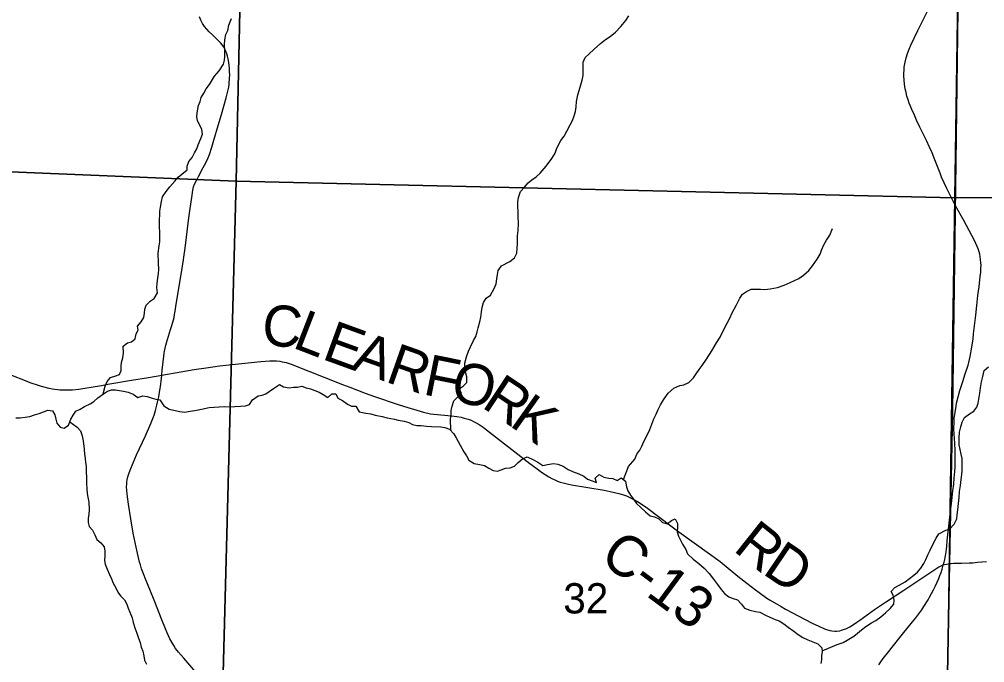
# Model space of a CAD drawing. Extents: x 0 to 34, y 0 to 22.
# Drawn here: x 15.148 to 16.483, y 14.243 to 15.132 of the extents above; entities that cross this region are included whole.
import ezdxf

# ---------------------------------------------------------------- set-up
doc = ezdxf.new("R2010")
doc.units = 0
for name, color, linetype in [('GM_X_Corporation', 7, 'Continuous'), ('GM_X_County_Road', 7, 'Continuous'), ('GM_X_County_Road_Text', 7, 'Continuous'), ('GM_X_Minor_River', 7, 'Continuous'), ('GM_X_Section_Text', 7, 'Continuous'), ('GM_X_Township_Road', 7, 'Continuous')]:
    doc.layers.add(name, color=color, linetype=linetype)

msp = doc.modelspace()

# ---------------------------------------------------------------- linework, layer by layer
at = {"layer": 'GM_X_Corporation'}
for points in [[(16.4214, 13.6), (17.4, 13.6), (17.4, 16.913), (16.5516, 16.9243), (16.4689, 16.9245), (16.4603, 16.2617), (16.4611, 16.1288), (16.4516, 15.5964), (16.4498, 15.4626), (16.4419, 14.8642), (16.438, 14.5908), (16.4339, 14.3806), (16.4212, 13.6609)], [(14.4583, 15.9623), (15.4691, 15.9163), (15.4475, 14.9085), (14.443, 14.9501)], [(15.4691, 15.9163), (16.4563, 15.9084), (16.441, 14.8856), (15.4475, 14.9085)], [(17.4, 14.8906), (17.4, 15.8967), (16.4563, 15.9084), (16.441, 14.8856)], [(14.443, 14.9501), (15.4475, 14.9085), (15.4212, 13.9143), (14.4181, 13.9369)], [(15.4475, 14.9085), (16.441, 14.8856), (16.4262, 13.901), (15.4212, 13.9143)], [(17.4, 13.8871), (17.4, 14.8906), (16.441, 14.8856), (16.4262, 13.901)]]:
    msp.add_lwpolyline(points, close=True, dxfattribs=at)
msp.add_lwpolyline([(10.9052, 15.3502), (10.897, 14.5214), (10.8818, 13.7678), (10.8788, 13.6), (16.4214, 13.6), (16.4212, 13.6609), (16.4339, 14.3806), (16.438, 14.5908), (16.4419, 14.8642), (16.4498, 15.4626)], dxfattribs=at)
at = {"layer": 'GM_X_County_Road'}
for points in [[(16.423, 14.9141), (16.4209, 14.9194), (16.4139, 14.9378), (16.4098, 14.9478), (16.4065, 14.9555), (16.4022, 14.9647), (16.393, 14.9833), (16.3884, 14.993), (16.3854, 14.9996), (16.3819, 15.0075), (16.3799, 15.0122), (16.3784, 15.0161), (16.3766, 15.021), (16.3751, 15.0261), (16.3739, 15.0309), (16.3728, 15.0359), (16.3722, 15.0393), (16.3718, 15.0424), (16.3713, 15.0484), (16.3709, 15.0537), (16.3714, 15.0662), (16.3725, 15.0728), (16.374, 15.0788), (16.376, 15.0851), (16.3781, 15.0907), (16.3805, 15.0965), (16.3902, 15.1169), (16.4059, 15.148)], [(16.442, 14.8754), (16.4303, 14.8983), (16.4264, 14.9063), (16.423, 14.9141)], [(16.4345, 14.4441), (16.4373, 14.4669), (16.4388, 14.4804), (16.4398, 14.4895), (16.4405, 14.4981), (16.4413, 14.507), (16.4416, 14.5133), (16.4419, 14.5212), (16.4418, 14.5361), (16.4413, 14.5462), (16.4402, 14.5656), (16.4403, 14.5758), (16.4406, 14.5804), (16.4408, 14.5832), (16.4417, 14.5887), (16.4431, 14.5976), (16.4438, 14.6014), (16.446, 14.6103), (16.4484, 14.6189), (16.4527, 14.6329), (16.4552, 14.6408), (16.4597, 14.654), (16.4607, 14.6577), (16.4618, 14.6619), (16.4626, 14.6661), (16.4649, 14.6792), (16.4665, 14.6906), (16.4673, 14.6972), (16.4702, 14.723), (16.4717, 14.7365), (16.4733, 14.7504), (16.4748, 14.7624), (16.4764, 14.7766), (16.4771, 14.7827), (16.4775, 14.788), (16.4776, 14.7922), (16.4775, 14.7954), (16.477, 14.8001), (16.4765, 14.8037), (16.4757, 14.8075), (16.4748, 14.811), (16.4736, 14.8147), (16.4723, 14.8181), (16.4704, 14.8225), (16.4685, 14.8263), (16.4537, 14.854), (16.4425, 14.8745), (16.442, 14.8754)], [(15.1366, 14.6403), (15.1556, 14.6327), (15.1622, 14.6303), (15.1737, 14.6263), (15.1776, 14.6252), (15.1885, 14.6225), (15.1936, 14.6215), (15.2037, 14.6201), (15.2058, 14.6199), (15.2209, 14.62), (15.2298, 14.6208), (15.2355, 14.6217), (15.2611, 14.6261), (15.2701, 14.6278), (15.3028, 14.6336), (15.3261, 14.6371), (15.3446, 14.6402), (15.3708, 14.6447), (15.3896, 14.6479), (15.4061, 14.6505), (15.4246, 14.6531), (15.4379, 14.6547), (15.4595, 14.657), (15.4816, 14.6591), (15.4942, 14.66), (15.4987, 14.6601), (15.5033, 14.6599), (15.5079, 14.6595), (15.5112, 14.6589), (15.5164, 14.6577), (15.5208, 14.6564), (15.5237, 14.6554), (15.5944, 14.6276), (15.6047, 14.6235), (15.6261, 14.6153), (15.6386, 14.611), (15.6717, 14.5996), (15.6847, 14.5956), (15.7019, 14.5903), (15.7067, 14.589), (15.7162, 14.587), (15.7208, 14.5863), (15.7451, 14.5841), (15.7527, 14.5832), (15.7585, 14.5822), (15.7628, 14.581), (15.7683, 14.5795), (15.7724, 14.5779), (15.7759, 14.5764), (15.7792, 14.5746), (15.7833, 14.5723), (15.7889, 14.5684), (15.7938, 14.5649), (15.8536, 14.5183), (15.8617, 14.512), (15.8698, 14.5062), (15.875, 14.5028), (15.8797, 14.4999), (15.884, 14.4975), (15.8884, 14.4954), (15.8919, 14.4939), (15.8957, 14.4925), (15.8996, 14.4914), (15.9071, 14.4896), (15.9112, 14.4888), (15.9564, 14.4811), (15.9646, 14.4796), (15.9705, 14.4783), (15.9767, 14.4766), (15.983, 14.4748), (15.9872, 14.4733), (15.9908, 14.4717), (15.9999, 14.4672), (16.0024, 14.4658), (16.0132, 14.4588), (16.0165, 14.4564), (16.0484, 14.4322), (16.0596, 14.4239), (16.1019, 14.3935), (16.1166, 14.3827), (16.1224, 14.3782), (16.1414, 14.3626), (16.1538, 14.3526), (16.1656, 14.3434), (16.1706, 14.3397), (16.1815, 14.3322), (16.186, 14.3293), (16.2012, 14.3203), (16.2072, 14.317), (16.2342, 14.3026), (16.2439, 14.2976), (16.2531, 14.2932), (16.261, 14.2898), (16.264, 14.2887), (16.2687, 14.2873), (16.2711, 14.2868), (16.2754, 14.2864), (16.2777, 14.2865), (16.2822, 14.2871), (16.2847, 14.2877), (16.2887, 14.289), (16.2907, 14.2898), (16.296, 14.2926), (16.2984, 14.294), (16.306, 14.299), (16.3101, 14.3018), (16.3202, 14.3089), (16.3304, 14.3163), (16.3385, 14.322), (16.3467, 14.3273), (16.3693, 14.3423), (16.3776, 14.3477), (16.4194, 14.3753), (16.4205, 14.376), (16.4232, 14.3771), (16.4254, 14.378)], [(16.3361, 14.2397), (16.3388, 14.244), (16.3421, 14.2486), (16.35, 14.2583), (16.3547, 14.2642), (16.3692, 14.2823), (16.3829, 14.2992), (16.3872, 14.3047), (16.3957, 14.3161), (16.3986, 14.3203), (16.4043, 14.3295), (16.4065, 14.3333), (16.4119, 14.3436), (16.4146, 14.3492), (16.4191, 14.3592), (16.4207, 14.3632), (16.4223, 14.3676), (16.4238, 14.3722), (16.4248, 14.3757), (16.4254, 14.378), (16.4264, 14.3817), (16.4274, 14.3855), (16.428, 14.3881), (16.4285, 14.3906), (16.4289, 14.3931), (16.4293, 14.3959), (16.4297, 14.3997), (16.4301, 14.4039), (16.4308, 14.4111), (16.4335, 14.4359), (16.4345, 14.4441)], [(16.4254, 14.378), (16.4272, 14.3786), (16.4299, 14.3792), (16.4323, 14.3796), (16.4332, 14.3797)], [(16.4332, 14.3797), (16.4344, 14.3799), (16.4362, 14.3801), (16.4396, 14.3804), (16.4507, 14.3806), (16.461, 14.3807), (16.4663, 14.381), (16.4729, 14.3816), (16.4786, 14.3823), (16.4851, 14.3829)]]:
    msp.add_lwpolyline(points, dxfattribs=at)
at = {"layer": 'GM_X_Minor_River'}
for points in [[(15.2636, 14.6143), (15.2664, 14.6253), (15.2693, 14.6315), (15.2737, 14.6369), (15.2809, 14.6394), (15.2861, 14.641), (15.2886, 14.6468), (15.2885, 14.6525), (15.2887, 14.6578), (15.2909, 14.6644), (15.2918, 14.6705), (15.2912, 14.6803), (15.2972, 14.6851), (15.3025, 14.6863), (15.308, 14.6907), (15.3094, 14.6972), (15.3119, 14.7025), (15.311, 14.7082), (15.3162, 14.7141), (15.3198, 14.7202), (15.3208, 14.726), (15.3211, 14.7313), (15.3232, 14.737), (15.3287, 14.7425), (15.334, 14.7464), (15.3387, 14.7542), (15.3378, 14.7614), (15.3384, 14.7671), (15.3393, 14.7747), (15.3399, 14.7808), (15.3405, 14.7865), (15.34, 14.7949), (15.3396, 14.8089), (15.3409, 14.8192), (15.3419, 14.8246), (15.3421, 14.8314), (15.3419, 14.8383), (15.3414, 14.8447), (15.3416, 14.8508), (15.3415, 14.8561), (15.3417, 14.8615), (15.3419, 14.8672), (15.3426, 14.8725), (15.3443, 14.8805), (15.3456, 14.887), (15.3508, 14.894), (15.3559, 14.9006), (15.3625, 14.9084), (15.3673, 14.9142), (15.3725, 14.9181), (15.3796, 14.924), (15.3795, 14.9293), (15.382, 14.9355), (15.3867, 14.9413), (15.39, 14.9475), (15.3933, 14.9532), (15.395, 14.9586), (15.3986, 14.9674), (15.4011, 14.9736), (15.4002, 14.98), (15.3974, 14.9857), (15.3942, 14.9917), (15.3933, 14.9977), (15.3935, 15.003), (15.3956, 15.013), (15.3977, 15.0187), (15.3991, 15.0241), (15.4027, 15.0303), (15.406, 15.036), (15.4104, 15.0422), (15.4177, 15.0538), (15.4239, 15.0612), (15.4298, 15.0701), (15.4312, 15.0755), (15.4318, 15.0808), (15.432, 15.0888), (15.4314, 15.0975), (15.432, 15.1036), (15.4333, 15.1112), (15.4358, 15.1166), (15.4375, 15.1243), (15.4411, 15.1335)], [(15.7444, 14.5638), (15.744, 14.5799), (15.7447, 14.5852), (15.7449, 14.5913), (15.7463, 14.5974), (15.7484, 14.6047), (15.7535, 14.6101), (15.7591, 14.6156), (15.7559, 14.6216), (15.7615, 14.6252), (15.7667, 14.6302), (15.7665, 14.6378), (15.7652, 14.6431), (15.7635, 14.6515), (15.7637, 14.6568), (15.7662, 14.6656), (15.7687, 14.6733), (15.7715, 14.6794), (15.7759, 14.6883), (15.7788, 14.6937), (15.7809, 14.7002), (15.7823, 14.7055), (15.7843, 14.714), (15.7857, 14.7205), (15.7866, 14.7277), (15.7876, 14.7338), (15.7894, 14.7407), (15.793, 14.7465), (15.7993, 14.7508), (15.8044, 14.7601), (15.8069, 14.7666), (15.8079, 14.7735), (15.8089, 14.7796), (15.8099, 14.7849), (15.8146, 14.7915), (15.8259, 14.7975), (15.8322, 14.8026), (15.8358, 14.8088), (15.836, 14.8156), (15.8366, 14.8221), (15.8367, 14.8331), (15.8373, 14.8404), (15.8378, 14.8495), (15.8376, 14.8594), (15.8371, 14.8799), (15.8377, 14.886), (15.8409, 14.8941), (15.8461, 14.9003), (15.8512, 14.9061), (15.8564, 14.9104), (15.8624, 14.9144), (15.868, 14.9195), (15.8761, 14.9292), (15.8838, 14.94), (15.8885, 14.947), (15.891, 14.9539), (15.8964, 14.9647), (15.9012, 14.9705), (15.9048, 14.9774), (15.9095, 14.9863), (15.9124, 14.9921), (15.9149, 14.9986), (15.9167, 15.0047), (15.9176, 15.0112), (15.9182, 15.0184), (15.9202, 15.028), (15.922, 15.0337), (15.9241, 15.0418), (15.9258, 15.0483), (15.9272, 15.0544), (15.9274, 15.0597), (15.9273, 15.0658), (15.9274, 15.073), (15.9299, 15.0792), (15.9351, 15.0839), (15.9426, 15.0909), (15.9515, 15.0987), (15.9581, 15.1042), (15.9649, 15.1085), (15.9719, 15.1144), (15.9793, 15.1222), (15.9863, 15.1307), (15.9907, 15.1369)], [(15.983, 14.496), (15.99, 14.5141), (15.9988, 14.5242), (16.0017, 14.5311), (16.0057, 14.5366), (16.0086, 14.5423), (16.0111, 14.5485), (16.0162, 14.5585), (16.0194, 14.565), (16.0223, 14.5727), (16.0251, 14.58), (16.0284, 14.5866), (16.0313, 14.5927), (16.0342, 14.5993), (16.0385, 14.6062), (16.0448, 14.6155), (16.0526, 14.6222), (16.0612, 14.6258), (16.0668, 14.6271), (16.0736, 14.6303), (16.0799, 14.6365), (16.0835, 14.6423), (16.0879, 14.6481), (16.092, 14.6536), (16.0978, 14.6625), (16.1051, 14.674), (16.1117, 14.6849), (16.1168, 14.6926), (16.1211, 14.7014), (16.1266, 14.7122), (16.1302, 14.7192), (16.1334, 14.7265), (16.1392, 14.7376), (16.1439, 14.7465), (16.1479, 14.7523), (16.1532, 14.7559), (16.1599, 14.7591), (16.1671, 14.7593), (16.1724, 14.759), (16.1785, 14.7588), (16.1861, 14.7597), (16.1963, 14.7615), (16.2053, 14.7648), (16.2135, 14.7684), (16.2195, 14.7712), (16.2255, 14.774), (16.2319, 14.7787), (16.2393, 14.785), (16.2445, 14.7916), (16.2511, 14.8005), (16.2551, 14.8075), (16.2568, 14.8132), (16.2604, 14.8205), (16.2637, 14.8271), (16.2684, 14.8336), (16.2724, 14.8429)], [(16.2579, 14.2592), (16.2787, 14.268), (16.287, 14.2709), (16.2926, 14.274), (16.3016, 14.2796), (16.3068, 14.2835), (16.3124, 14.2882), (16.3183, 14.2929), (16.3261, 14.2981), (16.3321, 14.3013), (16.3389, 14.306), (16.3455, 14.3119), (16.3518, 14.3177), (16.357, 14.3236), (16.3576, 14.3293), (16.3559, 14.3361), (16.3535, 14.3414), (16.3583, 14.3468), (16.3643, 14.35), (16.3729, 14.3548), (16.3785, 14.3591), (16.3845, 14.3638), (16.3897, 14.3681), (16.3945, 14.3736), (16.3985, 14.3798), (16.4014, 14.3855), (16.4042, 14.3921), (16.4071, 14.3982), (16.4104, 14.4055), (16.4154, 14.4152), (16.4191, 14.421), (16.4288, 14.4262), (16.4341, 14.4274), (16.4404, 14.4344), (16.444, 14.4417), (16.4446, 14.4471), (16.4456, 14.454), (16.4465, 14.4627), (16.4474, 14.4711), (16.448, 14.4795), (16.4493, 14.4879), (16.4502, 14.4959), (16.4512, 14.5028), (16.4514, 14.5081), (16.4513, 14.5146), (16.4515, 14.5199), (16.4514, 14.5252), (16.4501, 14.5313), (16.4475, 14.5441), (16.4473, 14.5536), (16.4478, 14.5613), (16.4496, 14.5689), (16.4517, 14.5751), (16.4545, 14.5816), (16.4616, 14.5867), (16.4676, 14.5907), (16.472, 14.5961), (16.4734, 14.6015), (16.4751, 14.6099), (16.4761, 14.6152), (16.477, 14.6228), (16.4784, 14.6312), (16.4801, 14.6385), (16.4821, 14.6469), (16.4881, 14.6516)], [(15.1427, 14.5812), (15.1488, 14.5813), (15.1556, 14.5823), (15.162, 14.5832), (15.1688, 14.5856), (15.1748, 14.5873), (15.1808, 14.5894), (15.1872, 14.5918), (15.1933, 14.5908), (15.1965, 14.5856), (15.1981, 14.5795), (15.1994, 14.5738), (15.2041, 14.5686), (15.2098, 14.5669), (15.2154, 14.5712), (15.219, 14.5793), (15.2219, 14.5851), (15.2259, 14.5905), (15.2315, 14.5933), (15.2379, 14.5972), (15.2454, 14.6005), (15.2506, 14.604), (15.2562, 14.6091), (15.264, 14.6146), (15.2696, 14.6182), (15.2749, 14.6199), (15.2806, 14.62), (15.2863, 14.619), (15.2916, 14.618), (15.2981, 14.617), (15.305, 14.6138), (15.3116, 14.6094), (15.3183, 14.6118), (15.3244, 14.6108), (15.3298, 14.6091), (15.3363, 14.6073), (15.342, 14.6063), (15.3475, 14.5981), (15.3548, 14.5933), (15.3697, 14.5899), (15.3762, 14.5893)], [(15.3762, 14.5893), (15.3837, 14.5906), (15.3902, 14.5915), (15.3996, 14.5933), (15.4102, 14.5955), (15.417, 14.596), (15.4238, 14.5966), (15.4314, 14.5968), (15.4397, 14.5966), (15.4458, 14.5971), (15.4534, 14.5973), (15.4606, 14.5979), (15.4658, 14.5999), (15.4702, 14.6061), (15.4781, 14.6116), (15.4834, 14.6125), (15.4886, 14.6145), (15.4991, 14.6217), (15.5073, 14.6272), (15.513, 14.6243), (15.5207, 14.623), (15.5267, 14.6235), (15.5324, 14.6236), (15.5384, 14.6249), (15.5442, 14.6228), (15.5503, 14.6214), (15.5564, 14.6189), (15.5622, 14.6168), (15.5679, 14.6135), (15.5741, 14.6095), (15.58, 14.6145), (15.5854, 14.6147), (15.5882, 14.6087), (15.5947, 14.6054), (15.6013, 14.6002), (15.607, 14.5973), (15.6131, 14.5975), (15.6175, 14.5896), (15.6266, 14.5876), (15.6338, 14.587), (15.6396, 14.5852), (15.6495, 14.5832), (15.6564, 14.5811), (15.6663, 14.5794), (15.6716, 14.578), (15.6796, 14.5767), (15.6861, 14.575), (15.6915, 14.5721), (15.6972, 14.5707), (15.7033, 14.5705), (15.7105, 14.5699), (15.7174, 14.5693), (15.7303, 14.5689), (15.736, 14.5679), (15.7425, 14.5657), (15.7487, 14.5594), (15.7519, 14.5538), (15.7571, 14.5437), (15.7622, 14.5343), (15.7658, 14.529), (15.7693, 14.523), (15.7767, 14.5183), (15.7839, 14.5166), (15.7908, 14.5152), (15.7969, 14.5119), (15.8027, 14.5087), (15.8088, 14.5077), (15.8141, 14.5093), (15.8201, 14.5118), (15.8265, 14.5123), (15.8322, 14.5143), (15.8373, 14.5194), (15.8433, 14.5245), (15.85, 14.5273), (15.8577, 14.5237), (15.8646, 14.5201), (15.8716, 14.5153), (15.878, 14.5166), (15.8863, 14.5184), (15.8924, 14.5174), (15.8997, 14.5145), (15.9066, 14.5101), (15.9128, 14.5072), (15.9212, 14.504), (15.9281, 14.5008), (15.9335, 14.4963), (15.94, 14.4942), (15.9458, 14.4917), (15.9441, 14.4981), (15.9497, 14.5028), (15.9558, 14.4992), (15.9627, 14.4978), (15.9684, 14.4976), (15.9745, 14.4947), (15.9801, 14.4983), (15.9859, 14.4938), (15.9873, 14.4859), (15.9893, 14.4802), (15.9929, 14.4742), (15.9968, 14.469), (16.0011, 14.463)], [(15.2174, 14.5756), (15.2276, 14.5685), (15.2323, 14.5633), (15.2347, 14.5565), (15.2361, 14.5493), (15.2371, 14.5379), (15.2376, 14.5311), (15.2386, 14.525), (15.2391, 14.5197), (15.24, 14.5144), (15.2405, 14.4908), (15.2411, 14.4828), (15.2413, 14.4768), (15.2425, 14.4715), (15.2438, 14.4647), (15.2441, 14.454), (15.2439, 14.4483), (15.2429, 14.4422), (15.2426, 14.4365), (15.2443, 14.4312), (15.2486, 14.426), (15.2522, 14.4196), (15.255, 14.4132), (15.2604, 14.4084), (15.2647, 14.4032), (15.266, 14.3971), (15.2658, 14.391), (15.2652, 14.3842), (15.2661, 14.3789), (15.2689, 14.3721), (15.2721, 14.3649), (15.2749, 14.3589), (15.2773, 14.3529), (15.2809, 14.3465), (15.2837, 14.3405), (15.2873, 14.3353), (15.2931, 14.3297), (15.2963, 14.3237), (15.2983, 14.318), (15.3003, 14.3128), (15.3036, 14.3049), (15.3052, 14.2984), (15.3073, 14.2909), (15.3102, 14.2837), (15.3126, 14.2769), (15.3146, 14.2709), (15.3163, 14.2645), (15.3184, 14.2588), (15.3196, 14.2524), (15.3209, 14.2463), (15.3233, 14.241)], [(16.0011, 14.463), (16.0073, 14.4575), (16.0135, 14.4512), (16.0201, 14.446), (16.0262, 14.4443), (16.032, 14.4417), (16.0371, 14.4365), (16.0435, 14.4348), (16.0495, 14.4395), (16.0548, 14.4419), (16.058, 14.4352), (16.0577, 14.4298), (16.0575, 14.4237), (16.0591, 14.4177), (16.0647, 14.4068), (16.0695, 14.3993), (16.0715, 14.3933), (16.0793, 14.3859), (16.0874, 14.38), (16.0948, 14.3737), (16.1018, 14.3663), (16.1077, 14.3584), (16.1132, 14.351), (16.1182, 14.3442), (16.1229, 14.3383), (16.1287, 14.3338), (16.1349, 14.3317), (16.1406, 14.3296), (16.1464, 14.3236), (16.1504, 14.3184), (16.158, 14.3156), (16.1657, 14.3135), (16.1718, 14.3129), (16.1806, 14.3081), (16.1929, 14.3024), (16.1982, 14.3006), (16.2048, 14.2966), (16.211, 14.2918), (16.2187, 14.2866), (16.2249, 14.2819), (16.231, 14.2778), (16.238, 14.2746), (16.2518, 14.2688), (16.2572, 14.2636), (16.2581, 14.258), (16.2571, 14.2526), (16.2569, 14.2469), (16.2562, 14.2416)]]:
    msp.add_lwpolyline(points, dxfattribs=at)
at = {"layer": 'GM_X_Township_Road'}
for points in [[(15.3835, 14.8676), (15.3868, 14.8892), (15.3877, 14.896), (15.3886, 14.9006), (15.3898, 14.9044), (15.3925, 14.9095), (15.3955, 14.915), (15.402, 14.9273), (15.4053, 14.9338), (15.4083, 14.94), (15.4106, 14.9455), (15.414, 14.9553), (15.4168, 14.9652), (15.4225, 14.9853), (15.4271, 15.0007), (15.4335, 15.0236), (15.4354, 15.0308), (15.4371, 15.0386), (15.4377, 15.0426), (15.4384, 15.0511), (15.4385, 15.0552), (15.4384, 15.06), (15.4382, 15.0645), (15.4378, 15.0684), (15.4372, 15.0724), (15.4365, 15.0775), (15.4356, 15.0812), (15.4345, 15.0845), (15.4333, 15.088), (15.4319, 15.091), (15.43, 15.0944), (15.428, 15.097), (15.4263, 15.0993), (15.4213, 15.1044), (15.4146, 15.1108), (15.4101, 15.1151), (15.4067, 15.1186), (15.4039, 15.1222), (15.4009, 15.1264), (15.3986, 15.1308), (15.3967, 15.1354)], [(15.3745, 14.7995), (15.3752, 14.8033), (15.377, 14.8159), (15.3822, 14.858), (15.3835, 14.8676)], [(15.3446, 14.6402), (15.3453, 14.6477), (15.346, 14.6546), (15.348, 14.6707), (15.3484, 14.6736), (15.3501, 14.6818), (15.3509, 14.685), (15.3566, 14.7034), (15.3583, 14.7089), (15.3606, 14.7168), (15.3615, 14.72), (15.3624, 14.724), (15.3632, 14.7288), (15.3642, 14.7351), (15.3726, 14.788), (15.3745, 14.7995)], [(15.4113, 14.2069), (15.3749, 14.2493), (15.3677, 14.2573), (15.3636, 14.2625), (15.3611, 14.2664), (15.3584, 14.2714), (15.3559, 14.276), (15.3522, 14.284), (15.3498, 14.2895), (15.3446, 14.3023), (15.3339, 14.3293), (15.329, 14.3415), (15.3217, 14.3595), (15.3202, 14.3635), (15.3167, 14.3728), (15.3151, 14.3779), (15.314, 14.3817), (15.3091, 14.4023), (15.3076, 14.4091), (15.3051, 14.4217), (15.3017, 14.4417), (15.2985, 14.4619), (15.2965, 14.4758), (15.2961, 14.4811), (15.2959, 14.4856), (15.2961, 14.4899), (15.2964, 14.4928), (15.2969, 14.4958), (15.2978, 14.4997), (15.2992, 14.5041), (15.3009, 14.5091), (15.3048, 14.519), (15.3098, 14.5301), (15.318, 14.5475), (15.3219, 14.5563), (15.3293, 14.5734), (15.3321, 14.5802), (15.3339, 14.5852), (15.3358, 14.5913), (15.3377, 14.5987), (15.3388, 14.6031), (15.3404, 14.6105), (15.3424, 14.6223), (15.3426, 14.624), (15.3442, 14.6363), (15.3446, 14.6402)]]:
    msp.add_lwpolyline(points, dxfattribs=at)

# ---------------------------------------------------------------- texts
at = {"layer": 'GM_X_County_Road_Text'}
for s, height, rotation, p in [('C', 0.0568, 354.1391, (15.4812, 14.6828)), ('L', 0.0568, 338.844, (15.5237, 14.679)), ('E', 0.0568, 340.0154, (15.5645, 14.6632)), ('A', 0.0568, 340.4769, (15.605, 14.6485)), ('R', 0.0568, 340.5988, (15.6522, 14.6318)), ('F', 0.0568, 348.5547, (15.7045, 14.614)), ('O', 0.0568, 346.4727, (15.7416, 14.6065)), ('R', 0.0568, 326.5113, (15.7854, 14.5969)), ('K', 0.0568, 324.7084, (15.8239, 14.5714)), ('R', 0.0568, 321.4828, (16.1334, 14.3986)), ('C-13', 0.05682, 323.4978, (15.9481, 14.3842)), ('D', 0.0568, 325.88, (16.1737, 14.3668))]:
    msp.add_text(s, height=height, rotation=rotation, dxfattribs=at).set_placement(p)
at = {"layer": 'GM_X_Section_Text'}
msp.add_text('32', height=0.04186, rotation=0, dxfattribs=at).set_placement((15.8998, 14.3109))

doc.saveas('drawing.dxf')
